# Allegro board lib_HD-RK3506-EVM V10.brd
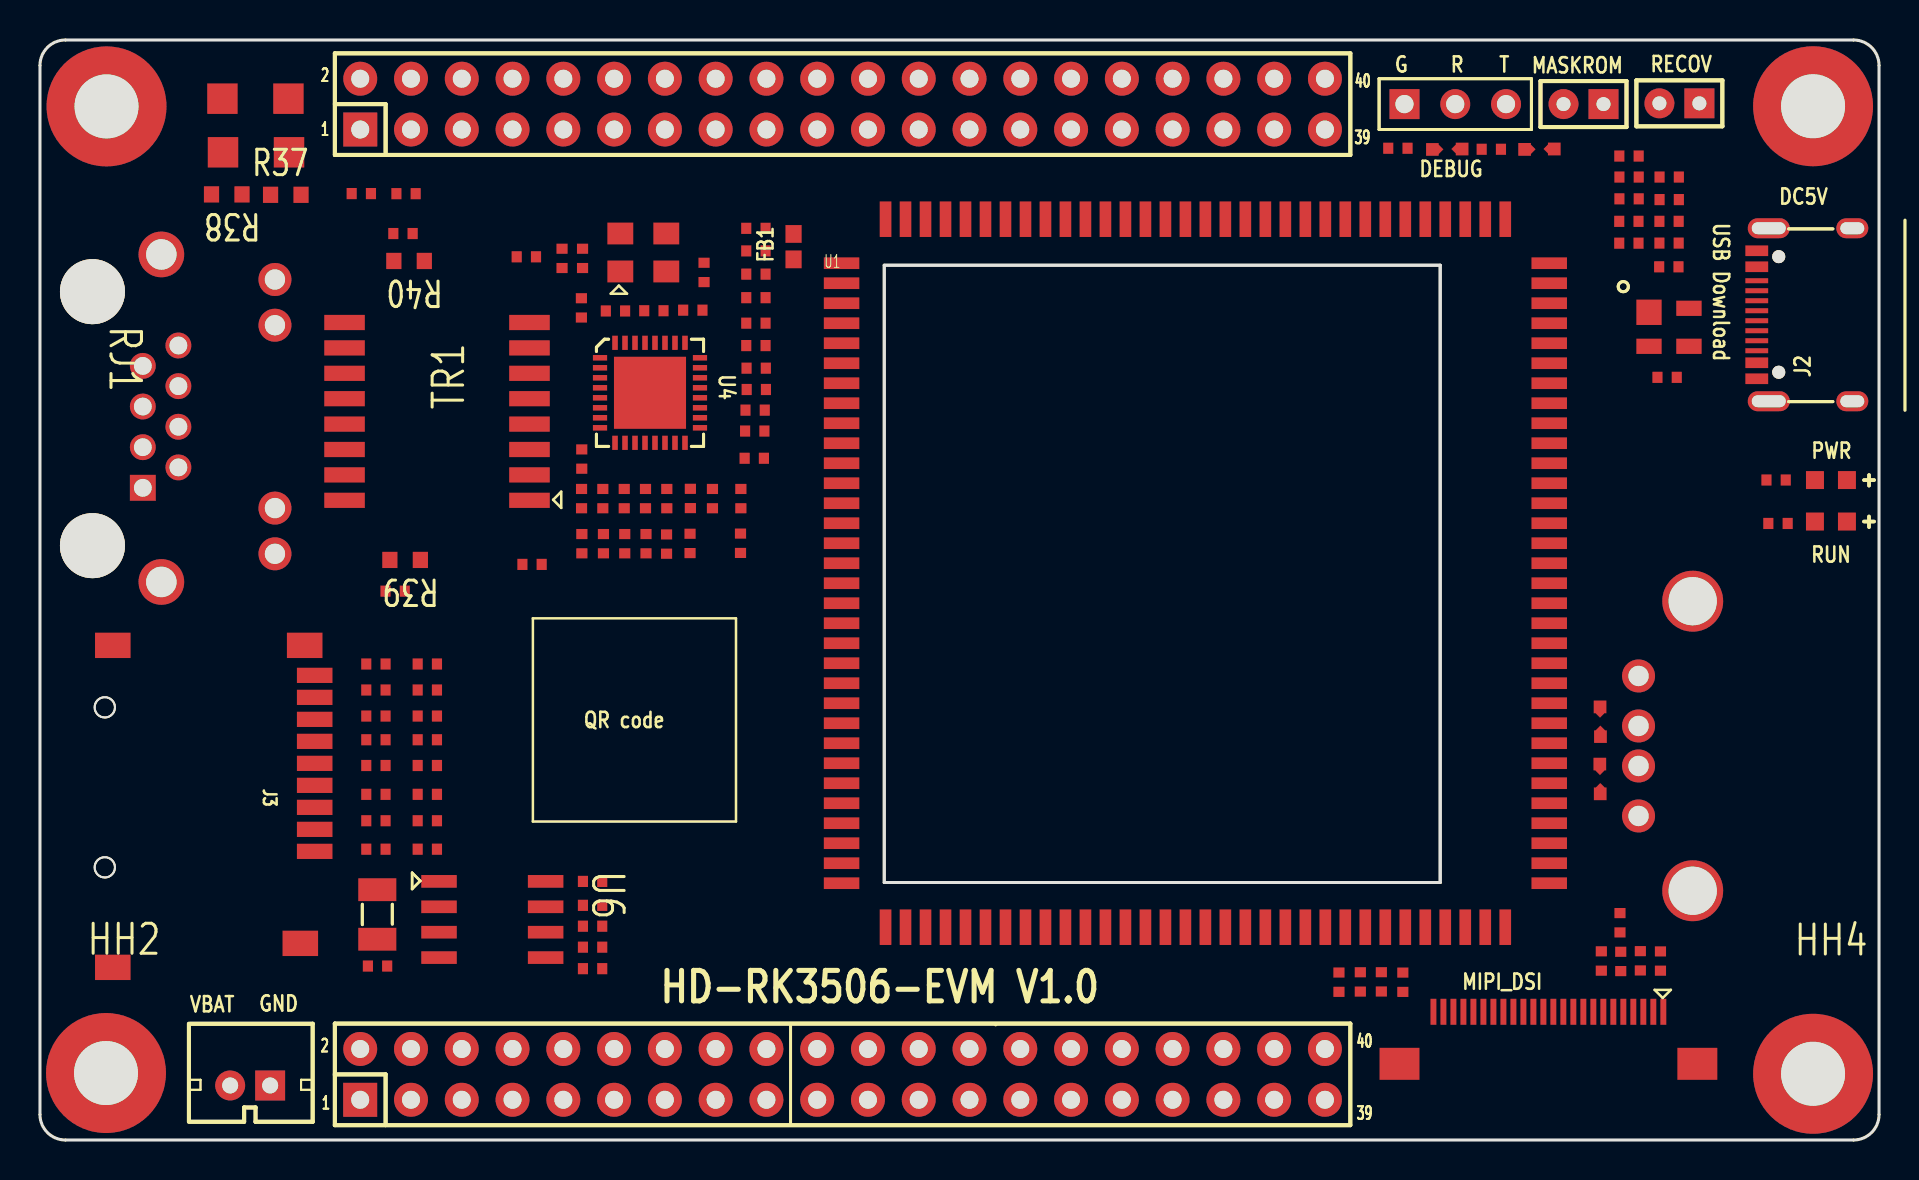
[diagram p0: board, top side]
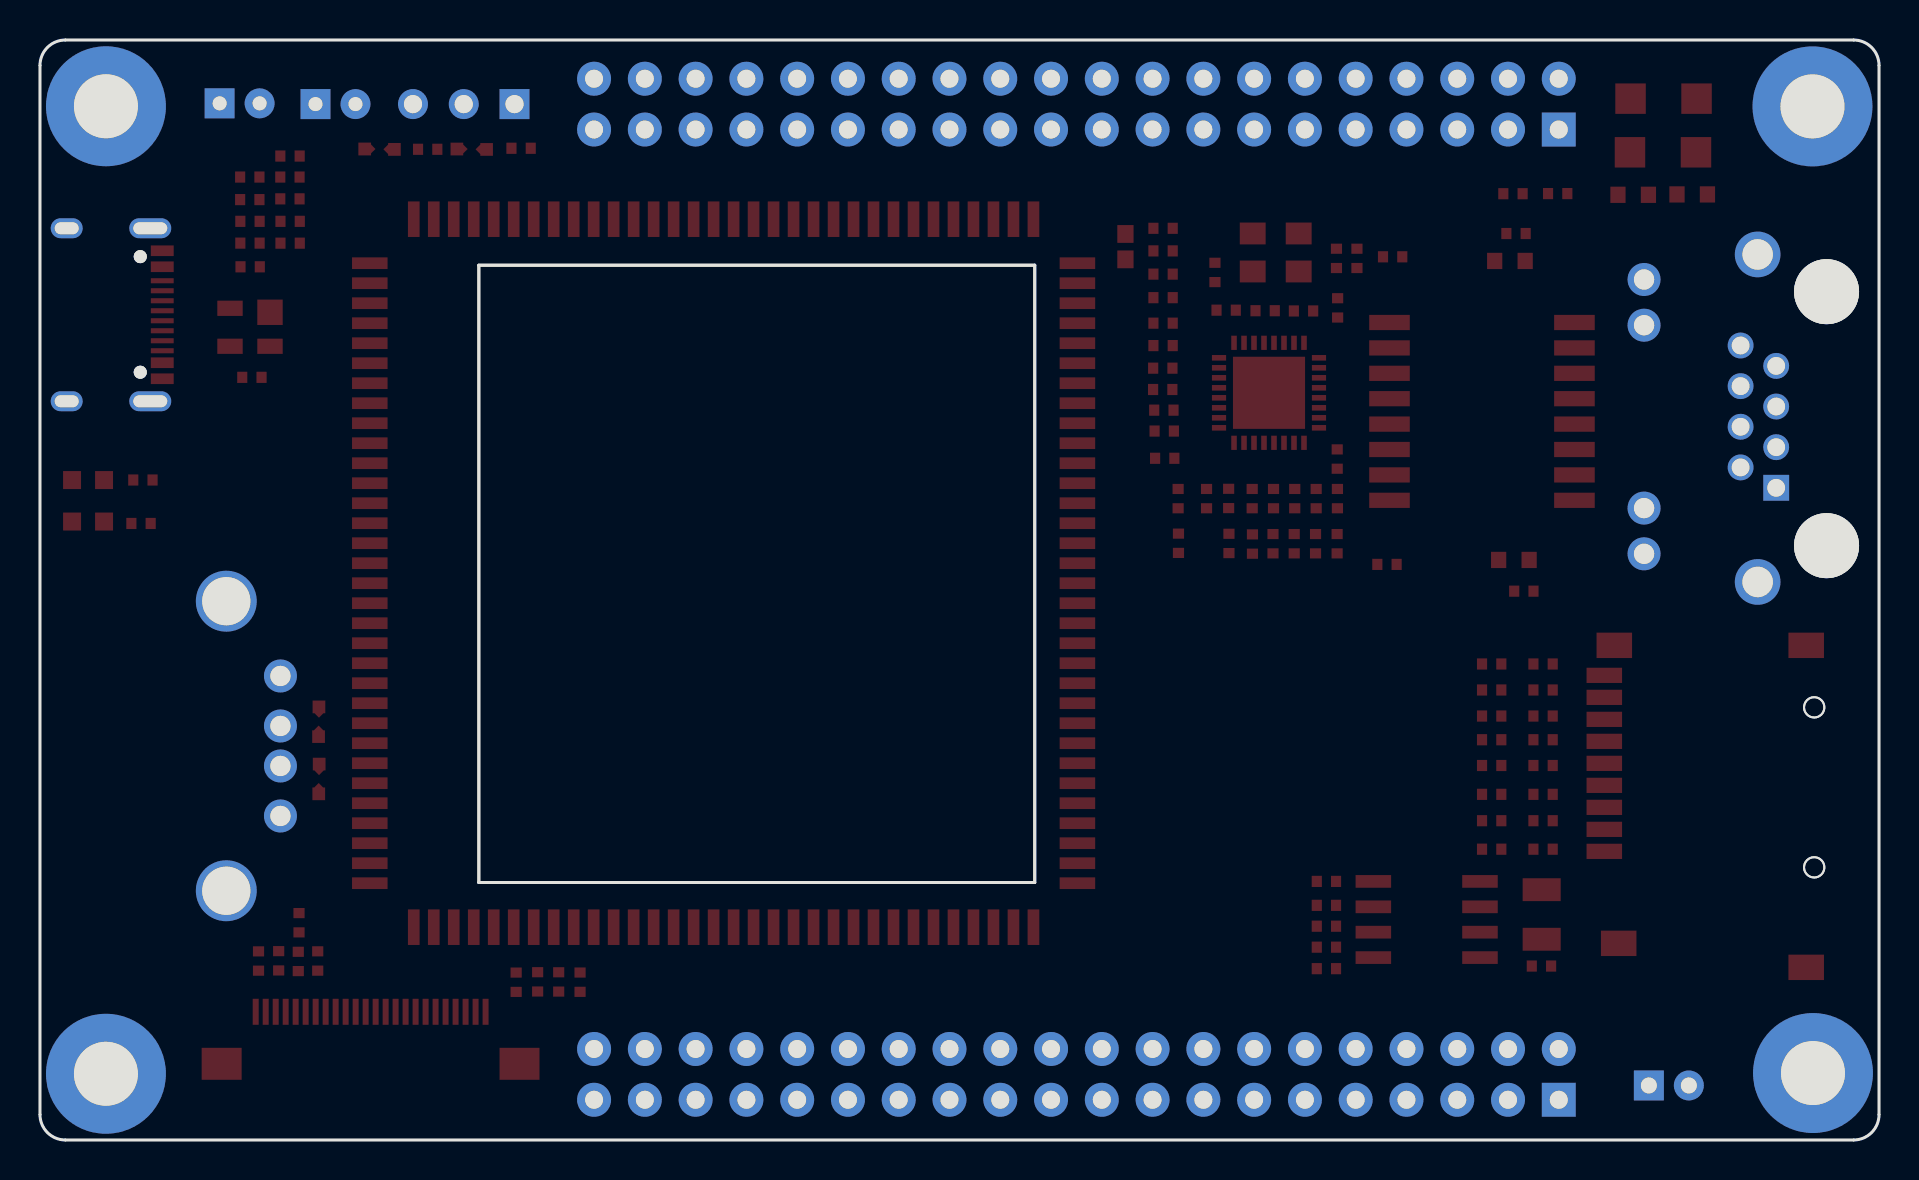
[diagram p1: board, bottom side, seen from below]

Outline 92 x 55 mm; copper layers: TOP, BOTTOM. Coordinates in mm from the lower left corner of the outline.
Outline path: circle c3.24,21.63 r0.51 ; circle c3.24,13.63 r0.51 ; 0,53.73 0,1.27 arc(0.37,0.37) 1.27,0 90.73,0 arc(91.63,0.37) 92,1.27 92,53.73 arc(91.63,54.63) 90.73,55 1.27,55 arc(0.37,54.63) 0,53.73 ; 42.24,43.74 42.24,12.87 70.04,12.87 70.04,43.74 42.24,43.74

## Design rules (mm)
net group CAP_SDA: nets CAP_SDA I2C2_SDA
net group DIFFPAIR0: nets P0_MDIN0 P0_MDIP0
net group DIFFPAIR1: nets P0_MDIN1 P0_MDIP1
net group ETH0_LED2: nets ETH0_LED2 N16931838
net group MIPI_CLK: nets MIPI_DPHY_DSI_TX_CLKN MIPI_DPHY_DSI_TX_CLKP
net group MIPI_D0: nets MIPI_DPHY_DSI_TX_D0N MIPI_DPHY_DSI_TX_D0P
net group MIPI_D1: nets MIPI_DPHY_DSI_TX_D1N MIPI_DPHY_DSI_TX_D1P
net group RMII1_RXDV_CRS: nets RMII1_RXDV_CRS RMII_RST_N
net group SDMMC_CLK: nets N16830486 SDMMC_CLK
net group SDMMC_D0: nets N16830419 SDMMC_D0
net group SDMMC_D1: nets N16830415 SDMMC_D1
net group USB20_OTG1: nets USB20_OTG1_DM USB20_OTG1_DP
net group SD3: nets N16830445 N16830451 N16830461

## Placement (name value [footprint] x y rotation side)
C8  10uF  [C0402]  27.11 29.82 270 top
C10  10uF  [C0402]  31.34 29.8 270 top
C12  0.1uF  [C0402]  32.54 32.08 270 top
C13  0.1uF  [C0402]  27.1 34.05 270 top
C14  22pF  [C0402]  30.71 41.46 180 top
C15  22pF  [C0402]  28.79 41.45 0 top
C16  10uF  [C0402]  26.12 44.08 90 top
C17  0.1uF  [C0402]  27.08 41.61 90 top
C18  10uF  [C0402]  33.22 43.38 90 top
C19  0.1uF  [C0402]  32.66 41.49 0 top
C20  0.1uF  [C0402]  35.73 34.09 0 top
C21  1000pF/2KV  [C1206]  10.81 49.39 180 top
C22  0.1uF  [C0402]  24.33 44.16 0 top
C23  0.1uF  [C0402]  24.62 28.78 0 top
C24  1000pF/2KV  [C1206]  10.78 52.07 180 top
C25  10uF  [C0402]  79.04 10.86 90 top
C26  10uF  [C0402]  19.38 18.73 0 top
C27  0.1uF  [C0402]  16.81 18.73 0 top
C28  10uF  [C0402]  79.08 8.93 90 top
C29  0.1uF  [C0402]  78.11 8.95 90 top
C30  10uF  [C0402]  80.06 8.96 90 top
C31  0.1uF  [C0402]  81.07 8.95 90 top
C32  0.1uF  [C0402]  27.64 12.93 0 top
C33  0.1uF  [C0402]  16.89 8.7 180 top
C34  10uF  [C0402]  18.31 47.32 0 top
C35  10uF  [C0402]  16.07 47.32 0 top
CN1  USBAF  [USB-AF-4P]  82.68 19.7 90 top
ED1  AZ5825-01F  [ESD0402]  75.02 49.55 0 top
ED2  AZ5825-01F  [ESD0402]  70.41 49.55 0 top
ED3  AZ5825-01F  [ESD0402]  78.05 18.04 270 top
ED4  AZ5825-01F  [ESD0402]  78.04 20.92 90 top
FB1  MLB1608-331P2A  [L0603]  37.7 44.67 270 top
HH1  HHH  [MTG1]  88.7 51.69 0 top
HH2  HHH  [MTG1]  3.3 3.35 0 top
HH3  HHH  [MTG1]  3.33 51.68 0 top
HH4  HHH  [MTG1]  88.7 3.31 0 top
J2  USB-TYPE-C  [TYPE_C_USB]  85.98 38.06 90 top
J3  TFCARD  [TFCARDT]  13.74 17.63 270 top
J4  CON24  [FPC-SMD_P0_50-24P_FGS-XJ-H2_0]  75.46 5.11 180 top
J5  CON2  [HDR200M-1X2]  83.01 51.83 180 top
J6  CON2  [HDR200M-1X2]  78.22 51.8 180 top
J7  CON3  [HDR1X3]  70.8 51.8 0 top
J8  CON40  [HDR254M-2X20]  16.02 2.01 0 top
J9  CON40  [HDR254M-2X20]  16.02 50.52 0 top
JP1  NC/HDR-1X2  [PH2_0-LI-2P]  10.51 2.73 180 top
LED1  OED-EL  [LED0603]  89.59 33 180 top
LED2  OED-EL  [LED0603]  89.59 30.92 180 top
R4  220R  [R0402]  86.85 33 180 top
R5  220R  [R0402]  86.94 30.83 180 top
R6  5.1K  [R0402]  81.48 43.66 0 top
R7  10K  [R0402]  67.1 7.91 270 top
R8  NC/10K  [R0402]  64.98 7.89 270 top
R9  15K  [R0402]  66.05 7.9 90 top
R10  5.1K  [R0402]  81.4 38.13 0 top
R11  4.7K  [R0402]  35.83 38.59 0 top
R13  4.7K  [R0402]  28.16 32.07 90 top
R14  22R  [R0402]  32.52 29.83 90 top
R15  22R  [R0402]  33.64 32.07 90 top
R16  4.7K  [R0402]  30.29 32.07 90 top
R17  22R  [R0402]  35.04 29.84 90 top
R18  22R  [R0402]  35.06 32.07 90 top
R19  NC/4.7K  [R0402]  35.82 43.29 180 top
R20  NC/4.7K  [R0402]  35.82 45.59 180 top
R21  22R  [R0402]  28.19 29.82 90 top
R22  22R  [R0402]  29.25 29.82 90 top
R23  22R  [R0402]  35.82 44.46 180 top
R24  2.49K/1%  [R0402]  27.14 44.08 270 top
R25  22R  [R0402]  35.82 39.72 180 top
R26  22R  [R0402]  35.83 37.53 180 top
R27  10K  [R0402]  35.76 35.45 0 top
R28  22R  [R0402]  35.78 36.49 0 top
R29  4.7K  [R0402]  27.09 32.07 270 top
R30  NC/4.7K  [R0402]  31.36 32.07 270 top
R31  4.7K  [R0402]  30.32 29.82 90 top
R32  4.7K  [R0402]  29.23 32.07 90 top
R33  4.7K  [R0402]  35.82 42.12 0 top
R34  4.7K  [R0402]  35.82 40.84 0 top
R35  1K  [R0402]  18.16 45.32 180 top
R36  1K  [R0402]  17.77 27.44 180 top
R37  75R  [R0603]  12.3 47.26 0 top
R38  75R  [R0603]  9.34 47.28 180 top
R39  75R  [R0603]  18.27 29 180 top
R40  75R  [R0603]  18.46 43.95 180 top
R41  10K  [R0402]  16.81 23.8 0 top
R42  10K  [R0402]  16.81 14.54 0 top
R43  10K  [R0402]  16.81 15.96 0 top
R44  NC/10K  [R0402]  16.81 17.28 0 top
R45  NC/10K  [R0402]  16.81 20.01 0 top
R46  NC/10K  [R0402]  16.81 21.2 0 top
R47  10K  [R0402]  16.81 22.5 0 top
R48  22R  [R0402]  19.38 22.5 180 top
R49  22R  [R0402]  19.38 21.2 180 top
R50  0R  [R0402]  19.38 20.01 180 top
R51  22R  [R0402]  19.38 17.28 180 top
R52  22R  [R0402]  19.38 15.96 180 top
R53  22R  [R0402]  19.38 14.54 180 top
R54  1K  [R0402]  19.38 23.8 180 top
R55  22R  [R0402]  79.49 45.93 0 top
R56  10K  [R0402]  81.49 45.94 180 top
R57  22R  [R0402]  79.49 44.84 0 top
R58  10K  [R0402]  81.49 44.85 180 top
R59  0R  [R0402]  79.49 48.15 0 top
R60  10K  [R0402]  81.5 48.15 180 top
R61  0R  [R0402]  79.49 47.06 0 top
R62  10K  [R0402]  81.5 47.02 180 top
R63  22R  [R0402]  79.49 49.2 0 top
R64  22R  [R0402]  68.18 7.89 90 top
R65  10K  [R0402]  27.64 8.57 0 top
R66  22R  [R0402]  27.64 9.64 180 top
R67  22R  [R0402]  27.64 10.69 180 top
R68  10K  [R0402]  27.64 11.73 0 top
R69  100R  [R0402]  72.6 49.54 180 top
R70  100R  [R0402]  67.93 49.59 180 top
RJ1  RJ45  [RJ45_LED_T5J]  5.14 38.71 270 top
TR1  TRANSFORMER_H1102NL  [SSIC16]  19.86 36.43 90 top
U1  Stamp hole  [SMD_RK3506B-B-128P]  40.3 10.84 0 top
U3  UET14A05L03  [SOT143B]  81.49 40.64 270 top
U4  YT8512C  [QFN32_5X5]  30.52 37.36 0 top
U6  NC/RS4C1338  [SOP8-50-150]  22.63 11.03 270 top
Y1  25MHz  [S3225A]  30.18 44.38 0 top
Y2  NC/32.768KHz  [3215]  16.88 11.28 270 top

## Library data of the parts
C8 C10 C12-C20 C22 C23 C26-C31 C34 C35 = CAP_NP
C21 = CAP_Dup2_C46: Tolerance: TOL; User Part Number: PN
C24 = CAP NP2_2: Tolerance: TOL; User Part Number: PN
C25 = C_1
C32 C33 = CAP_NP_3
CN1 = USBAF
ED1-ED4 = DIODE BI_DIR TRIG
FB1 = FBEAD_0
HH1-HH4 = HHH
J2 = USBCF_0
J3 = SD
J4 = CON24
J5 J6 = CON2: User Part Number: partnum; Tolerance: RichardLC
J7 = CON3
J8 J9 = CON40A: User Part Number: partnum; Tolerance: RichardLC
JP1 = Header 2_JP6
LED1 LED2 = OED-EL
R4 R5 = R
R6 R7 R9 R10 R13-R27 R29 R31 R33 R35 R39 R40 R46 R51-R58 R60-R68 = RES
R8 = RES: signal model: DEFAULT_RESISTOR_100000OHM_2_1
R11 = RES: signal model: RES_R0402_DISCRETE_1K_1K
R28 R30 R32 R34 R36 R41-R45 R49 R50 R59 = RES: signal model: RES_R0402_DISCRETE_22R_22R
R37 = RES_R82
R38 = RES_R83
R47 R48 = RES: signal model: RES_R0402_DISCRETE_0R_0R
R69 R70 = 22OhmResistor1/16W1%0603
RJ1 = RJ45
TR1 = TRANSFORMER_H1102NL
U1 = Stamp hole
U3 = PRTR5V0U2X
U4 = YT8512
U6 = ISL1208
Y1 = CRY4_13
Y2 = Crystal_32_0

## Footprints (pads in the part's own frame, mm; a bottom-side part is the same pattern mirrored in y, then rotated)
3215
  rect 1.143x1.905 smd: 1(-1.239,0) 2(1.239,0)
C0402
  rect 0.508x0.559 smd: 1(-0.483,0) 2(0.483,0)
C1206
  rect 1.524x1.524 smd: 1(-1.651,0) 2(1.651,0)
ESD0402
  custom 0.159x0.159 smd: 1(-0.635,-0.02) 2(0.622,0)
FPC-SMD_P0_50-24P_FGS-XJ-H2_0
  rect 0.3x1.3 smd: 1(-5.748,-1.301) 2(-5.248,-1.301) 3(-4.748,-1.301) 4(-4.248,-1.301) 5(-3.748,-1.301) 6(-3.248,-1.301) 7(-2.748,-1.301) 8(-2.248,-1.301) 9(-1.748,-1.301) 10(-1.248,-1.301) 11(-0.748,-1.301) 12(-0.248,-1.301) 13(0.252,-1.301) 14(0.752,-1.301) 15(1.252,-1.301) 16(1.752,-1.301) 17(2.252,-1.301) 18(2.752,-1.301) 19(3.252,-1.301) 20(3.752,-1.301) 21(4.252,-1.301) 22(4.752,-1.301) 23(5.252,-1.301) 24(5.752,-1.301)
  rect 2x1.6 smd: 25(7.45,1.301) 26(-7.45,1.301)
HDR1X3
  rect 1.5x1.5 hole 0.91: 1(-2.54,0)
  round 1.5 hole 0.91: 2(0,0) 3(2.54,0)
HDR200M-1X2
  rect 1.5x1.5 hole 0.7: 1(0,0)
  round 1.5 hole 0.7: 2(2,0)
HDR254M-2X20
  rect 1.7x1.7 hole 0.9: 1(0,0)
  round 1.7 hole 0.9: 2(0,2.54) 3(2.54,0) 4(2.54,2.54) 5(5.08,0) 6(5.08,2.54) 7(7.62,0) 8(7.62,2.54) 9(10.16,0) 10(10.16,2.54) 11(12.7,0) 12(12.7,2.54) 13(15.24,0) 14(15.24,2.54) 15(17.78,0) 16(17.78,2.54) 17(20.32,0) 18(20.32,2.54) 19(22.86,0) 20(22.86,2.54) 21(25.4,0) 22(25.4,2.54) 23(27.94,0) 24(27.94,2.54) 25(30.48,0) 26(30.48,2.54) 27(33.02,0) 28(33.02,2.54) 29(35.56,0) 30(35.56,2.54) 31(38.1,0) 32(38.1,2.54) 33(40.64,0) 34(40.64,2.54) 35(43.18,0) 36(43.18,2.54) 37(45.72,0) 38(45.72,2.54) 39(48.26,0) 40(48.26,2.54)
L0603
  rect 0.889x0.813 smd: 1(-0.635,0) 2(0.635,0)
LED0603
  rect 0.899x0.899 smd: 1(-0.8,0) 2(0.8,0)
MTG1
  round 6 hole 3.2: 1(0,0)
PH2_0-LI-2P
  rect 1.5x1.5 hole 0.8: 1(-1,0)
  round 1.5 hole 0.8: 2(1,0)
QFN32_5X5
  rect 0.711x0.279 smd: 1(-2.5,1.75) 2(-2.5,1.25) 3(-2.5,0.75) 4(-2.5,0.25) 5(-2.5,-0.25) 6(-2.5,-0.75) 7(-2.5,-1.25) 8(-2.5,-1.75) 17(2.5,-1.75) 18(2.5,-1.25) 19(2.5,-0.75) 20(2.5,-0.25) 21(2.5,0.25) 22(2.5,0.75) 23(2.5,1.25) 24(2.5,1.75)
  rect 0.279x0.711 smd: 9(-1.75,-2.5) 10(-1.25,-2.5) 11(-0.75,-2.5) 12(-0.25,-2.5) 13(0.25,-2.5) 14(0.75,-2.5) 15(1.25,-2.5) 16(1.75,-2.5) 25(1.75,2.5) 26(1.25,2.5) 27(0.75,2.5) 28(0.25,2.5) 29(-0.25,2.5) 30(-0.75,2.5) 31(-1.25,2.5) 32(-1.75,2.5)
  rect 3.607x3.607 smd: 33(0,0)
R0402
  rect 0.508x0.559 smd: 1(-0.483,0) 2(0.483,0)
R0603
  rect 0.762x0.813 smd: 1(-0.762,0) 2(0.762,0)
RJ45_LED_T5J
  round 3.251 hole 3.251 unplated: (-3.712,-2.52) (8.988,-2.52)
  rect 1.295x1.295 hole 0.889: 1(6.096,0)
  round 1.295 hole 0.889: 2(5.076,1.78) 3(4.064,0) 4(3.044,1.78) 5(2.032,0) 6(1.012,1.78) 7(0,0) 8(-1.02,1.78)
  round 1.651 hole 1.016: 9(-4.32,6.61) 10(-2.034,6.61) 11(7.11,6.61) 12(9.396,6.61)
  round 2.286 hole 1.524: 13(-5.573,0.927) 14(10.803,0.927)
S3225A
  rect 1.295x1.092 smd: 1(-1.15,-0.95) 2(1.15,-0.95) 3(1.15,0.95) 4(-1.15,0.95)
SMD_RK3506B-B-128P
  rect 1.778x0.584 smd: 1(-0.2,33) 2(-0.2,32) 3(-0.2,31) 4(-0.2,30) 5(-0.2,29) 6(-0.2,28) 7(-0.2,27) 8(-0.2,26) 9(-0.2,25) 10(-0.2,24) 11(-0.2,23) 12(-0.2,22) 13(-0.2,21) 14(-0.2,20) 15(-0.2,19) 16(-0.2,18) 17(-0.2,17) 18(-0.2,16) 19(-0.2,15) 20(-0.2,14) 21(-0.2,13) 22(-0.2,12) 23(-0.2,11) 24(-0.2,10) 25(-0.2,9) 26(-0.2,8) 27(-0.2,7) 28(-0.2,6) 29(-0.2,5) 30(-0.2,4) 31(-0.2,3) 32(-0.2,2) 65(35.2,2) 66(35.2,3) 67(35.2,4) 68(35.2,5) 69(35.2,6) 70(35.2,7) 71(35.2,8) 72(35.2,9) 73(35.2,10) 74(35.2,11) 75(35.2,12) 76(35.2,13) 77(35.2,14) 78(35.2,15) 79(35.2,16) 80(35.2,17) 81(35.2,18) 82(35.2,19) 83(35.2,20) 84(35.2,21) 85(35.2,22) 86(35.2,23) 87(35.2,24) 88(35.2,25) 89(35.2,26) 90(35.2,27) 91(35.2,28) 92(35.2,29) 93(35.2,30) 94(35.2,31) 95(35.2,32) 96(35.2,33)
  rect 0.584x1.778 smd: 33(2,-0.2) 34(3,-0.2) 35(4,-0.2) 36(5,-0.2) 37(6,-0.2) 38(7,-0.2) 39(8,-0.2) 40(9,-0.2) 41(10,-0.2) 42(11,-0.2) 43(12,-0.2) 44(13,-0.2) 45(14,-0.2) 46(15,-0.2) 47(16,-0.2) 48(17,-0.2) 49(18,-0.2) 50(19,-0.2) 51(20,-0.2) 52(21,-0.2) 53(22,-0.2) 54(23,-0.2) 55(24,-0.2) 56(25,-0.2) 57(26,-0.2) 58(27,-0.2) 59(28,-0.2) 60(29,-0.2) 61(30,-0.2) 62(31,-0.2) 63(32,-0.2) 64(33,-0.2) 97(33,35.2) 98(32,35.2) 99(31,35.2) 100(30,35.2) 101(29,35.2) 102(28,35.2) 103(27,35.2) 104(26,35.2) 105(25,35.2) 106(24,35.2) 107(23,35.2) 108(22,35.2) 109(21,35.2) 110(20,35.2) 111(19,35.2) 112(18,35.2) 113(17,35.2) 114(16,35.2) 115(15,35.2) 116(14,35.2) 117(13,35.2) 118(12,35.2) 119(11,35.2) 120(10,35.2) 121(9,35.2) 122(8,35.2) 123(7,35.2) 124(6,35.2) 125(5,35.2) 126(4,35.2) 127(3,35.2) 128(2,35.2)
SOP8-50-150
  rect 0.635x1.778 smd: 1(-1.905,-2.667) 2(-0.635,-2.667) 3(0.635,-2.667) 4(1.905,-2.667) 5(1.905,2.667) 6(0.635,2.667) 7(-0.635,2.667) 8(-1.905,2.667)
SOT143B
  rect 1.27x1.27 smd: 1(-0.75,-1)
  rect 0.762x1.27 smd: 2(0.95,-1) 3(0.95,1) 4(-0.95,1)
SSIC16
  rect 0.762x2.032 smd: 1(-4.445,-4.625) 2(-3.175,-4.625) 3(-1.905,-4.625) 4(-0.635,-4.625) 5(0.635,-4.625) 6(1.905,-4.625) 7(3.175,-4.625) 8(4.445,-4.625) 9(4.445,4.625) 10(3.175,4.625) 11(1.905,4.625) 12(0.635,4.625) 13(-0.635,4.625) 14(-1.905,4.625) 15(-3.175,4.625) 16(-4.445,4.625)
TFCARDT
  rect 0.762x1.778 smd: 1(3.2,0) 2(2.1,0) 3(1,0) 4(-0.1,0) 5(-1.2,0) 6(-2.3,0) 7(-3.4,0) 8(-4.5,0) 9(-5.6,0)
  rect 1.27x1.778 smd: 10(-7.1,-0.5) 11(7.8,-0.72) 12(-7.1,-10.1) 13(9,-10.1)
TYPE_C_USB
  round 0.65 hole 0.65 unplated: (0.325,-1) (6.105,-1)
  rect 0.533x1.143 smd: 1(0,0.1) 2(0.8,0.1) 11(5.6,0.1) 12(6.4,0.1)
  rect 0.254x1.143 smd: 3(1.4,0.1) 4(1.9,0.1) 5(2.4,0.1) 6(2.9,0.1) 7(3.4,0.1) 8(3.9,0.1) 9(4.4,0.1) 10(4.9,0.1)
  oval 1.001x2.101 hole 0.599x1.699: 13(-1.125,-0.5) 14(7.525,-0.5)
  oval 1.001x1.6 hole 0.599x1.199: 15(-1.125,-4.68) 16(7.525,-4.68)
USB-AF-4P
  round 1.651 hole 1.016: 1(-3.5,2.71) 2(-1,2.71) 3(1,2.71) 4(3.5,2.71)
  round 3.048 hole 2.413: 5(-7.239,0) 6(7.239,0)

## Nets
3V3_PHY: C8.1 C10.1 C12.1 C13.1 C26.1 C27.1 C28.1 C29.1 C32.1 C34.1 J3.4(VDD) J4.3 J4.4 J9.1 J9.3 LED1.1(ANODE) LED2.1(ANODE) R11.2 R13.1 R16.1 R27.2 R29.2 R30.2 R41.2 R42.2 R43.2 R44.2 R45.2 R46.2 R47.2 R60.1 R62.1 R65.2 R68.2 U1.5 U1.6 U4.7(AVDD33) U4.14(DVDD33) U6.8(VDD)
AVDDL_O: C16.1 C17.1 U4.2(AVDDL_O)
DVDDL_O: C18.1 C19.1 U4.29(DVDDL_OUT)
GND: C8.2 C10.2 C12.2 C13.2 C14.1 C15.1 C16.2 C17.2 C18.2 C19.2 C20.2 C22.2 C23.2 C25.1(A) C26.2 C27.2 C28.2 C29.2 C30.2 C31.2 C32.2 C33.2 C34.2 C35.2 CN1.4 CN1.5 CN1.6 ED1.2 ED2.2 ED3.2 ED4.2 HH1.1 HH2.1 HH3.1 HH4.1 J2.1(GND1) J2.12(GND2) J2.13 J2.14 J2.15 J2.16 J3.6(GND) J3.10(GROUND) J3.11(PAD3) J3.12(PAD1) J3.13(PAD2) J4.8 J4.11 J4.14 J4.17 J4.18 J4.23 J4.24 J4.25 J4.26 J5.1 J6.1 J7.1 J8.19 J8.39 J8.40 J9.12 J9.13 J9.22 J9.39 J9.40 JP1.1 R4.2 R6.1 R8.2 R9.1 R10.1 R19.1 R20.1 R24.1 R31.1 R32.1 R33.2 R34.2 R56.1 R58.1 RJ1.10(P10) RJ1.12(P12) U1.9 U1.10 U1.11 U1.12 U1.22 U1.32 U1.33 U1.54 U1.59 U1.62 U1.65 U1.68 U1.71 U1.84 U1.93 U1.102 U1.110 U1.123 U1.128 U3.1 U4.33(EP) U6.4(GND) Y1.2 Y1.4
GND_EARTH: C21.2 C24.2 RJ1.13(P13)
VBAT: C33.1 JP1.2 U6.3(VBAT)
VCC5V0_SYS: FB1.2 U1.1 U1.2 U1.3 U1.4
VCC_1V8: U1.7 U1.8
ACODEC_ADC_INN: J8.37 U1.53
ACODEC_ADC_INP: J8.38 U1.52
CAN0_RX: J9.20 U1.120(RM_IO20)
CAN0_TX: J9.21 U1.119(RM_IO19)
CAN1_RX: J9.18 U1.122(RM_IO18)
CAN1_TX: J9.19 U1.121(RM_IO13)
CAP_RST: J4.22 R64.2
CAP_SCL: J4.19 R61.2 R62.2
CAP_SDA: J4.20 R59.2 R60.2
CAP_TS_INT: J4.21 R63.2
ETH0_LED1: R34.1 R35.1 U4.24(LED0/PHYAD0)
ETH0_LED2: R33.1 R36.1 U4.25(LED1/PHYAD1)
FSPI_CLK: J8.23 U1.44
FSPI_CSN: J8.26 U1.45
FSPI_D0: J8.20 U1.40
FSPI_D1: J8.22 U1.41
FSPI_D2: J8.21 U1.42
FSPI_D3: J8.24 U1.43
GPIO0_D0_D: U1.51
I2C2_SCL: R61.1 U1.103(RM_IO4)
I2C2_SDA: R59.1 U1.104(RM_IO5)
IICSCL: R67.2 R68.1 U6.6(SCL)
IICSDA: R65.1 R66.2 U6.5(SDA)
LCD_PWREN: J4.5 R55.2 R56.2
MIPI_DPHY_DSI_TX_CLKN: J4.15 U1.63
MIPI_DPHY_DSI_TX_CLKP: J4.16 U1.64
MIPI_DPHY_DSI_TX_D0N: J4.9 U1.69
MIPI_DPHY_DSI_TX_D0P: J4.10 U1.70
MIPI_DPHY_DSI_TX_D1N: J4.12 U1.66
MIPI_DPHY_DSI_TX_D1P: J4.13 U1.67
NPOR_L: J8.25 U1.46
P0_MDIN0: RJ1.2(P2) TR1.11(RX1+)
P0_MDIN1: RJ1.6(P6) TR1.16(TX1+)
P0_MDIN_0: TR1.6(RD+) U4.4(TXN0)
P0_MDIN_1: TR1.1(TD+) U4.6(TXN1)
P0_MDIP0: RJ1.1(P1) TR1.9(RX-)
P0_MDIP1: RJ1.3(P3) TR1.14(TX1-)
P0_MDIP_0: TR1.8(RD-) U4.3(TXP0)
P0_MDIP_1: TR1.3(TD-) U4.5(TXP1)
PWM_LCD: J4.6 R57.2 R58.2
RMII0_CLK: R14.1 U1.29
RMII0_MDC: R26.1 U1.25
RMII0_MDIO: R25.1 U1.24
RMII0_RXD0: R21.1 U1.31
RMII0_RXD1: R22.1 U1.30
RMII0_RXDV_CRS: R23.1 U1.23
RMII0_TXD0: R15.1 U1.28
RMII0_TXD1: R17.1 U1.27
RMII0_TXEN: R18.1 U1.26
RMII1_CLK: J9.6 U1.19
RMII1_MDC: J9.10 U1.15
RMII1_MDIO: J9.9 U1.14
RMII1_RXD0: R54.1 U1.21
RMII1_RXD1: J9.5 U1.20
RMII1_RXDV_CRS: R28.2 U1.13
RMII1_TXD0: J9.7 U1.18
RMII1_TXD1: J9.8 U1.17
RMII1_TXEN: J9.11 U1.16
RMII_CLK: R14.2 U4.15(TXC)
RMII_CRS_DV: R19.2 R23.2 U4.26(CRS/CRS_DV)
RMII_MDC: R26.2 U4.22(MDC)
RMII_MDIO: R11.1 R25.2 U4.23(MDIO)
RMII_RST_N: C20.1 R27.1 R28.1 U4.21(RESET_N)
RMII_RXD0: R13.2 R21.2 U4.9(RXD0)
RMII_RXD1: R22.2 R32.2 U4.10(RXD1)
RMII_RXD3: R30.1 R31.2 U4.12(RXD3/CLK_CTL)
RMII_RXER: R20.2 U4.28(RXER)
RMII_TXD0: R15.2 U4.16(TXD0)
RMII_TXD1: R17.2 U4.17(TXD1)
RMII_TXEN: R18.2 U4.20(TX_EN)
RXDV: R29.1 U4.8(RX_DV)
SAI1_LRCK: R57.1 U1.107(RM_IO10)
SAI1_MCLK: J9.31 U1.105(RM_IO8)
SAI1_SCLK: R63.1 U1.106(RM_IO9)
SAI1_SDI: J9.30 U1.108(RM_IO11)
SAI1_SDO0: J9.29 U1.109(RM_IO12)
SARADC_IN0_BOOT: J6.2 U1.48
SARADC_IN1_RECOVER/KEY: J5.2 U1.47
SARADC_IN2: J8.36 U1.49
SARADC_IN3: J8.35 U1.50
SDMMC_CLK: R50.1 U1.34
SDMMC_CMD: R51.1 U1.35
SDMMC_D0: R49.1 U1.36
SDMMC_D1: R48.1 U1.37
SDMMC_D2: R53.1 U1.38
SDMMC_D3: R52.1 U1.39
SPI0_CLK: J9.17 U1.124(RM_IO1)
SPI0_CSN0: J9.14 U1.127(RM_IO7)
SPI0_MISO: J9.15 U1.126(RM_IO6)
SPI0_MOSI: J9.16 U1.125(RM_IO3)
UART0_RX/JTAG_TMS_M1: R70.2(P2) U1.112(RM_IO23)
UART0_TX/JTAG_TCK_M1: R69.2(P2) U1.111(RM_IO22)
UART1_RX: J9.27 U1.114(RM_IO16)
UART1_TX: J9.28 U1.113(RM_IO17)
UART2_RX: J9.25 U1.116(RM_IO0)
UART2_TX: J9.26 U1.115(RM_IO2)
UART3_RX: J9.23 U1.118(RM_IO15)
UART3_TX: J9.24 U1.117(RM_IO14)
USB20_OTG0_DM: J2.5(D1-) J2.7(D2-) U1.56 U3.3
USB20_OTG0_DP: J2.6(D1+) J2.8(D2+) U1.55 U3.2
USB20_OTG0_ID: R8.1 U1.57
USB20_OTG0_VBUSDET: R7.1 R9.2 U1.58
USB20_OTG1_DM: CN1.2 ED3.1 U1.61
USB20_OTG1_DP: CN1.3 ED4.1 U1.60
USBV: C25.2(B) C30.1 C31.1 C35.1 CN1.1 FB1.1 J2.2(VCC1) J2.11(VCC2) J4.1 J4.2 J9.2 J9.4 R7.2 U3.4
VO_LCDC_CLK: J8.30 U1.75
VO_LCDC_D0: R55.1 U1.101(RM_IO31)
VO_LCDC_D1: J9.32 U1.100(RM_IO30)
VO_LCDC_D2: J9.33 U1.99(RM_IO29)
VO_LCDC_D3: J9.34 U1.98
VO_LCDC_D4: J9.35 U1.97
VO_LCDC_D5: J9.36 U1.96
VO_LCDC_D6: J9.37 U1.95
VO_LCDC_D7: J9.38 U1.94
VO_LCDC_D8: U1.92(RM_IO28)
VO_LCDC_D9: U1.91(RM_IO27)
VO_LCDC_D10: U1.90
VO_LCDC_D11: U1.89
VO_LCDC_D12: U1.88
VO_LCDC_D13: U1.87
VO_LCDC_D14: U1.86
VO_LCDC_D15: R64.1 U1.85
VO_LCDC_D16: R5.2 U1.83(RM_IO26)
VO_LCDC_D17: R67.1 U1.82(RM_IO25)
VO_LCDC_D18: R66.1 U1.81(RM_IO24)
VO_LCDC_D19: J8.33 U1.80
VO_LCDC_D20: J8.34 U1.79
VO_LCDC_D21: J8.31 U1.78
VO_LCDC_D22: J8.32 U1.77
VO_LCDC_D23: J8.29 U1.76
VO_LCDC_DEN: U1.72
VO_LCDC_HSYNC: J8.27 U1.74
VO_LCDC_VSYNC: J8.28 U1.73
XTAL_25M_IN: C14.2 U4.31(XTAL_IN) Y1.3
XTAL_25M_OUT: C15.2 U4.32(XTAL_OUT) Y1.1
N16785592: R24.2 U4.1(RBIAS)
N16785729: R16.2 U4.11(RXD2/INT_N)
N16802850: C24.1 R39.1 R40.1
N16802854: C23.1 TR1.2(TCT)
N16802937: R39.2 TR1.15(TXCT)
N16802941: R40.2 TR1.10(RXCT)
N16802947: C22.1 TR1.7(RCT)
N16822745: U6.2(X2) Y2.2
N16822747: U6.1(X1) Y2.1
N16824705: LED1.2(CATHODE) R4.1
N16824707: LED2.2(CATHODE) R5.1
N16830378: J3.9(SD) R41.1 R54.2
N16830415: J3.8(DAT1) R47.1 R48.2
N16830419: J3.7(DAT0) R46.1 R49.2
N16830445: J3.2(CD/DAT3) R43.1 R52.2
N16830451: J3.3(CMD) R44.1 R51.2
N16830461: J3.1(DAT2) R42.1 R53.2
N16830486: J3.5(CLK) R45.1 R50.2
N16838991: ED2.1 J7.2 R70.1(P1)
N16839038: ED1.1 J7.3 R69.1(P1)
N16869521: J2.4 R10.2
N16869524: J2.10 R6.2
N16931068: R37.2 RJ1.4(P4) RJ1.5(P5)
N16931070: R38.2 RJ1.7(P7) RJ1.8(P8)
N16931090: C21.1 R37.1 R38.1
N16931828: R35.2 RJ1.9(P9)
N16931838: R36.2 RJ1.11(P11)

Pads without a net: J2 3 9; J4 7; J8 1 2 3 4 5 6 7 8 9 10 11 12 13 14 15 16 17 18; RJ1 14; TR1 4 5 12 13; U4 13 18 19 27 30; U6 7

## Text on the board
User.Comments: CR_1_2 | CR_1_1 | CR_YT8512_1 | CR_222_3 | CR_222_2
Ref Des/Silkscreen Top: 2 | 1 | 39 | 40 | VBAT | GND | QR code | G | DEBUG | R | MIPI_DSI | T | MASKROM | RECOV | DC5V | RUN | PWR | USB Download | HD-RK3506-EVM V1.0
BODY_CENTER: FIGURE | SIZE | 7.9 | 27.559 | 31.5 | 35.0 | 35.433 | 35.83 | 40.0 | 60.0 | 95.0 | 125.984 | 25.6 | 128.0 | 47.2x23.6 | 66.9x23.6 | DRILL CHART: TOP to BOTTOM | ALL UNITS ARE IN MILS | TOLERANCE | +0.0/-0.0 | +3.0/-3.0 | +2.0/-2.0 | PLATED | NON-PLATED | QTY | 345 | 4 | 2 | 8 | 80 | 3
